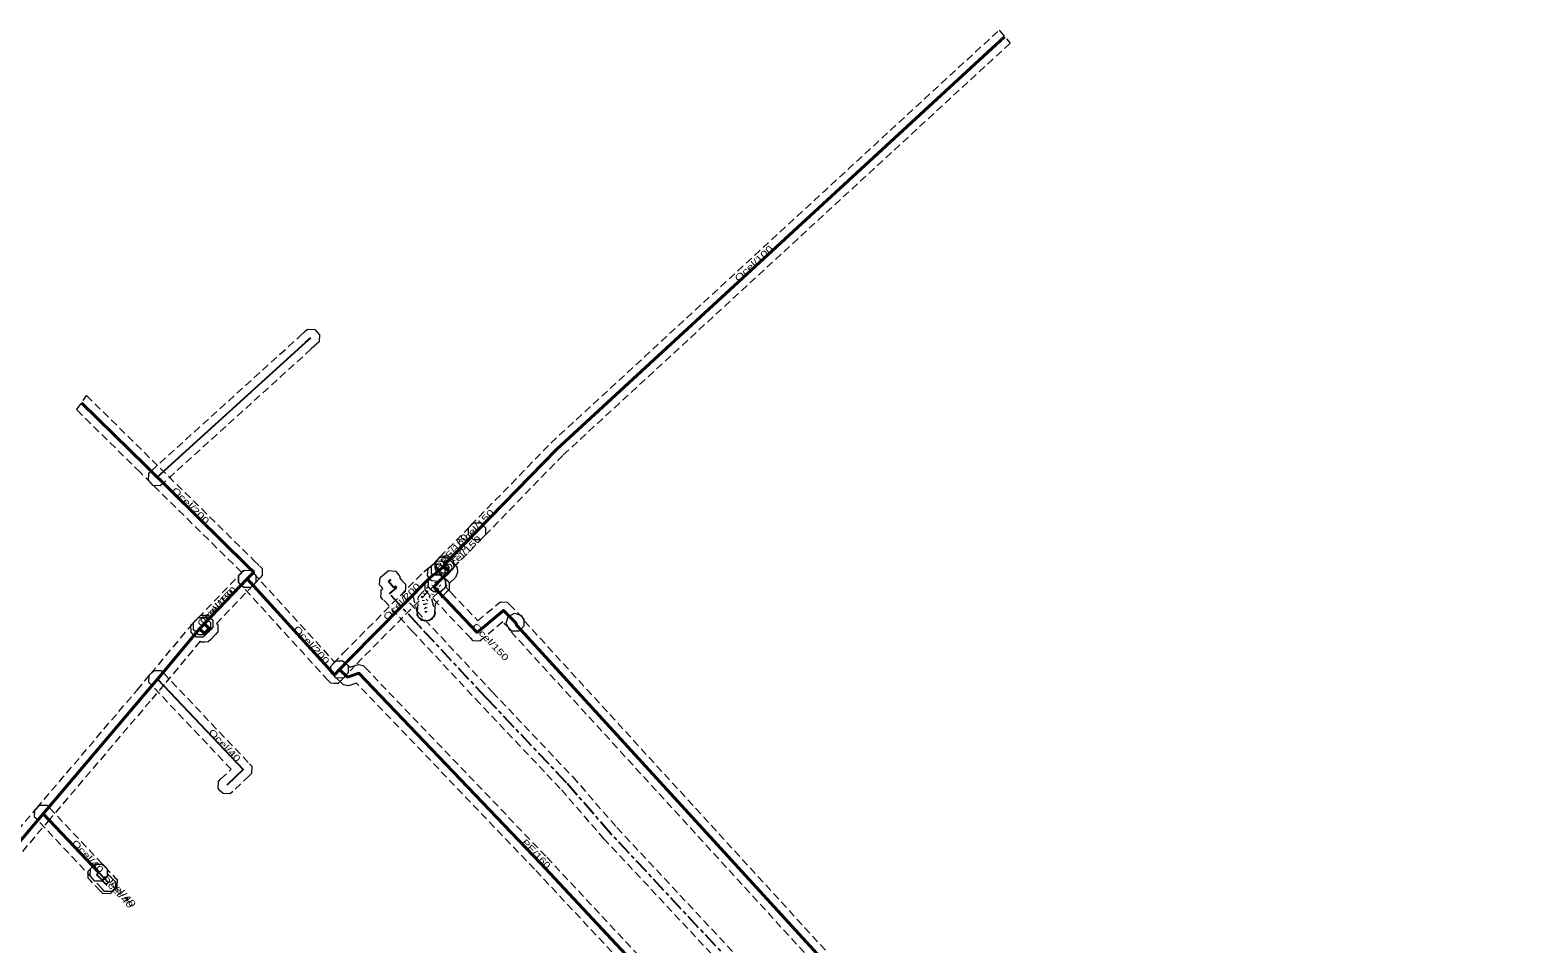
# Model space of a CAD drawing. Extents: x -588392 to -586332, y -1208963 to -1206334.
# Drawn here: x -588303.3 to -588126.9, y -1206440.6 to -1206333.7 of the extents above; entities that cross this region are included whole.
import ezdxf

# ---------------------------------------------------------------- set-up
doc = ezdxf.new("R2010")
doc.units = 0
doc.header["$LTSCALE"] = 0.3
for name, pattern in [('DOTTED', [1.5, 0.3, -1.2]), ('LONG_DASH_SHORT_DASH', [9.9, 6, -1.2, 1.5, -1.2]), ('MEDIUM_DASHED', [4.5, 3, -1.5])]:
    doc.linetypes.add(name, pattern=pattern)
for name, color, linetype, lineweight in [('1', 7, 'MEDIUM_DASHED', 13), ('24', 7, 'Continuous', 25), ('25', 7, 'Continuous', 25), ('51', 7, 'MEDIUM_DASHED', 13), ('55', 7, 'LONG_DASH_SHORT_DASH', 25), ('56', 7, 'DOTTED', 35), ('7', 7, 'MEDIUM_DASHED', 13), ('8', 7, 'MEDIUM_DASHED', 13)]:
    doc.layers.add(name, color=color, linetype=linetype, lineweight=lineweight)
doc.layers.add('30', color=7, linetype='Continuous')

msp = doc.modelspace()

# ---------------------------------------------------------------- linework, layer by layer
at = {"layer": '1'}
for points in [[(-588242.398, -1206381.993), (-588189.949, -1206333.691), (-588188.651, -1206335.214), (-588241.002, -1206383.427), (-588250.323, -1206393.007), (-588250.612, -1206393.304), (-588251.44, -1206393.316), (-588251.737, -1206393.027), (-588252.034, -1206392.738), (-588252.046, -1206391.91), (-588251.757, -1206391.613)], [(-588290.461, -1206385.403), (-588297.883, -1206378.097), (-588296.716, -1206376.439), (-588289.059, -1206383.977), (-588277.168, -1206395.678), (-588276.458, -1206396.378), (-588276.165, -1206396.666), (-588276.154, -1206397.487), (-588276.439, -1206397.783), (-588277.199, -1206398.573), (-588277.486, -1206398.872), (-588278.315, -1206398.888), (-588278.613, -1206398.601), (-588278.912, -1206398.314), (-588278.928, -1206397.485), (-588278.641, -1206397.187), (-588278.566, -1206397.109), (-588278.572, -1206397.102)], [(-588255.814, -1206395.829), (-588255.54, -1206395.518), (-588255.374, -1206395.33), (-588251.757, -1206391.613), (-588251.468, -1206391.316), (-588250.64, -1206391.304), (-588250.343, -1206391.593), (-588250.046, -1206391.882), (-588250.034, -1206392.71), (-588250.323, -1206393.007), (-588253.906, -1206396.69), (-588254.04, -1206396.842), (-588254.314, -1206397.152), (-588255.141, -1206397.204), (-588255.452, -1206396.93), (-588255.762, -1206396.656)], [(-588254.86, -1206397.679), (-588255.183, -1206397.939), (-588255.909, -1206398.524), (-588265.252, -1206407.956), (-588266.385, -1206409.149), (-588266.67, -1206409.449), (-588267.499, -1206409.47), (-588267.799, -1206409.185), (-588268.099, -1206408.9), (-588268.12, -1206408.071), (-588267.835, -1206407.771), (-588266.688, -1206406.564), (-588257.251, -1206397.036), (-588256.437, -1206396.381), (-588256.114, -1206396.121), (-588255.291, -1206396.21), (-588255.031, -1206396.533), (-588254.771, -1206396.856)], [(-588256.764, -1206396.648), (-588256.443, -1206396.386), (-588256.003, -1206396.026), (-588255.682, -1206395.764), (-588254.858, -1206395.846), (-588254.596, -1206396.167), (-588254.334, -1206396.488), (-588254.416, -1206397.312), (-588254.737, -1206397.574), (-588255.177, -1206397.934), (-588255.498, -1206398.196), (-588256.322, -1206398.114), (-588256.584, -1206397.793), (-588256.846, -1206397.472)], [(-588256.358, -1206397.634), (-588256.15, -1206397.431), (-588256.378, -1206397.194), (-588256.362, -1206396.366), (-588256.063, -1206396.079), (-588255.846, -1206395.871), (-588255.687, -1206395.686), (-588255.414, -1206395.37), (-588254.996, -1206395.342), (-588254.579, -1206395.314), (-588254.267, -1206395.592), (-588253.64, -1206396.148), (-588253.488, -1206396.375), (-588253.348, -1206396.585), (-588253.301, -1206397.086), (-588253.398, -1206397.318), (-588253.557, -1206397.694), (-588254.958, -1206399.064), (-588255.01, -1206399.114), (-588255.306, -1206399.404), (-588256.134, -1206399.396), (-588256.424, -1206399.1), (-588256.714, -1206398.804), (-588256.706, -1206397.976), (-588256.41, -1206397.686)], [(-588255.956, -1206395.993), (-588255.683, -1206395.681), (-588255.543, -1206395.521), (-588255.27, -1206395.21), (-588254.443, -1206395.154), (-588254.131, -1206395.427), (-588253.82, -1206395.7), (-588253.764, -1206396.527), (-588254.037, -1206396.839), (-588254.177, -1206396.999), (-588254.45, -1206397.31), (-588255.277, -1206397.366), (-588255.589, -1206397.093), (-588255.9, -1206396.82)], [(-588277.181, -1206397.207), (-588267.694, -1206407.623), (-588267.548, -1206407.47), (-588266.72, -1206407.45), (-588266.42, -1206407.736), (-588266.12, -1206408.022), (-588266.1, -1206408.85), (-588266.386, -1206409.15), (-588266.986, -1206409.78), (-588267.286, -1206410.095), (-588267.721, -1206410.09), (-588268.156, -1206410.085), (-588268.449, -1206409.763), (-588278.659, -1206398.553), (-588278.938, -1206398.247), (-588278.9, -1206397.42), (-588278.593, -1206397.141), (-588278.287, -1206396.862), (-588277.46, -1206396.9)], [(-588254.7, -1206398.79), (-588254.719, -1206398.81), (-588254.154, -1206399.403), (-588254.087, -1206399.473), (-588250.952, -1206402.762), (-588248.591, -1206400.792), (-588248.293, -1206400.544), (-588247.517, -1206400.579), (-588247.243, -1206400.853), (-588245.833, -1206402.263), (-588245.54, -1206402.556), (-588245.54, -1206403.384), (-588245.833, -1206403.677), (-588246.126, -1206403.97), (-588246.954, -1206403.97), (-588247.247, -1206403.677), (-588248.011, -1206402.913), (-588250.389, -1206404.898), (-588250.692, -1206405.151), (-588251.481, -1206405.106), (-588251.754, -1206404.82), (-588255.533, -1206400.855), (-588255.6, -1206400.785), (-588256.465, -1206399.877), (-588256.824, -1206399.5), (-588257.1, -1206399.21), (-588257.1, -1206398.41), (-588256.825, -1206398.121), (-588256.474, -1206397.753), (-588256.434, -1206397.71), (-588256.148, -1206397.41), (-588255.32, -1206397.39), (-588255.02, -1206397.676), (-588254.72, -1206397.962)], [(-588284.503, -1206403.294), (-588284.213, -1206402.999), (-588283.921, -1206402.702), (-588283.631, -1206402.407), (-588282.802, -1206402.4), (-588282.507, -1206402.69), (-588282.212, -1206402.98), (-588282.205, -1206403.809), (-588282.495, -1206404.104), (-588282.787, -1206404.401), (-588283.077, -1206404.696), (-588283.906, -1206404.703), (-588284.201, -1206404.413), (-588284.496, -1206404.123)], [(-588284.212, -1206402.998), (-588283.922, -1206402.702), (-588283.654, -1206402.429), (-588283.364, -1206402.134), (-588282.535, -1206402.126), (-588282.239, -1206402.416), (-588281.944, -1206402.706), (-588281.936, -1206403.535), (-588282.226, -1206403.831), (-588282.494, -1206404.104), (-588282.784, -1206404.399), (-588283.613, -1206404.407), (-588283.909, -1206404.117), (-588284.204, -1206403.827)], [(-588287.979, -1206408.601), (-588287.694, -1206408.902), (-588277.664, -1206419.492), (-588277.379, -1206419.793), (-588277.402, -1206420.621), (-588277.702, -1206420.906), (-588279.622, -1206422.726), (-588279.923, -1206423.011), (-588280.751, -1206422.989), (-588281.036, -1206422.688), (-588281.321, -1206422.387), (-588281.299, -1206421.559), (-588280.998, -1206421.274), (-588279.803, -1206420.142), (-588289.146, -1206410.278), (-588289.431, -1206409.977), (-588289.409, -1206409.149), (-588289.108, -1206408.864), (-588288.807, -1206408.579)], [(-588301.347, -1206424.352), (-588301.063, -1206424.654), (-588294.563, -1206431.544), (-588294.278, -1206431.845), (-588294.302, -1206432.673), (-588294.604, -1206432.957), (-588294.905, -1206433.242), (-588295.733, -1206433.218), (-588296.017, -1206432.916), (-588302.517, -1206426.026), (-588302.802, -1206425.725), (-588302.778, -1206424.897), (-588302.476, -1206424.613), (-588302.175, -1206424.328)], [(-588294.29, -1206431.816), (-588294.29, -1206432.322), (-588293.635, -1206433.011), (-588293.35, -1206433.311), (-588293.371, -1206434.139), (-588293.671, -1206434.425), (-588293.971, -1206434.71), (-588294.799, -1206434.689), (-588295.085, -1206434.389), (-588296.255, -1206433.159), (-588296.535, -1206432.864), (-588296.525, -1206432.051), (-588296.237, -1206431.763), (-588295.997, -1206431.523), (-588295.704, -1206431.23), (-588294.876, -1206431.23), (-588294.583, -1206431.523)], [(-588294.846, -1206431.242), (-588294.562, -1206431.544), (-588293.432, -1206432.744), (-588293.148, -1206433.046), (-588293.172, -1206433.874), (-588293.474, -1206434.158), (-588293.776, -1206434.442), (-588294.604, -1206434.418), (-588294.888, -1206434.116), (-588296.018, -1206432.916), (-588296.302, -1206432.614), (-588296.278, -1206431.786), (-588295.976, -1206431.502), (-588295.674, -1206431.218)]]:
    msp.add_lwpolyline(points, close=True, dxfattribs=at)
for points in [[(-588308.256, -1206431.407), (-588302.552, -1206424.692), (-588290.804, -1206410.875), (-588289.187, -1206408.948), (-588284.267, -1206403.059), (-588283.988, -1206402.725), (-588283.934, -1206402.722), (-588283.663, -1206402.439), (-588278.643, -1206397.189), (-588278.357, -1206396.89), (-588277.528, -1206396.871), (-588277.229, -1206397.157), (-588276.93, -1206397.443), (-588276.911, -1206398.272), (-588277.197, -1206398.571), (-588281.534, -1206403.106), (-588281.372, -1206403.274), (-588281.368, -1206404.077), (-588281.644, -1206404.368), (-588282.194, -1206404.948), (-588282.481, -1206405.251), (-588282.898, -1206405.26), (-588283.315, -1206405.269), (-588283.422, -1206405.166), (-588287.653, -1206410.232), (-588289.276, -1206412.165), (-588301.028, -1206425.988), (-588306.724, -1206432.693)], [(-588105.041, -1206560.272), (-588137.218, -1206521.444), (-588141.774, -1206516.649), (-588169.516, -1206487.445), (-588190.167, -1206465.706), (-588196.423, -1206459.121), (-588203.622, -1206451.542), (-588247.155, -1206403.949), (-588247.425, -1206403.435), (-588247.618, -1206403.068), (-588247.372, -1206402.277), (-588247.005, -1206402.085), (-588246.638, -1206401.892), (-588245.847, -1206402.138), (-588245.655, -1206402.505), (-588245.505, -1206402.791), (-588202.158, -1206450.178), (-588194.973, -1206457.743), (-588188.717, -1206464.328), (-588168.066, -1206486.067), (-588140.324, -1206515.271), (-588135.722, -1206520.116), (-588103.501, -1206558.996)], [(-588226.031, -1206451.373), (-588244.316, -1206431.807), (-588265.143, -1206410.06), (-588265.852, -1206410.298), (-588266.115, -1206410.386), (-588266.656, -1206410.267), (-588266.858, -1206410.076), (-588267.798, -1206409.186), (-588268.099, -1206408.901), (-588268.121, -1206408.073), (-588267.836, -1206407.772), (-588267.551, -1206407.471), (-588266.723, -1206407.449), (-588266.422, -1206407.734), (-588265.919, -1206408.211), (-588265.178, -1206407.962), (-588264.903, -1206407.87), (-588264.339, -1206408.008), (-588264.138, -1206408.218), (-588242.864, -1206430.433), (-588224.569, -1206450.007)]]:
    msp.add_lwpolyline(points, dxfattribs=at)
at = {"layer": '24', "lineweight": 40}
for p, q in [((-588255.81, -1206397.16), (-588255.37, -1206396.8)), ((-588254.93, -1206396.34), (-588254.79, -1206396.18)), ((-588283.5, -1206403.7), (-588283.208, -1206403.403)), ((-588283.208, -1206403.403), (-588282.94, -1206403.13)), ((-588301.79, -1206425.34), (-588295.29, -1206432.23))]:
    msp.add_line(p, q, dxfattribs=at)
at = {"layer": '24'}
msp.add_line((-588295.29, -1206432.23), (-588294.16, -1206433.43), dxfattribs=at)
at = {"layer": '24', "lineweight": 40}
for points in [[(-588189.3, -1206334.453), (-588241.7, -1206382.71), (-588251.04, -1206392.31)], [(-588297.299, -1206377.268), (-588289.76, -1206384.69), (-588277.87, -1206396.39), (-588277.16, -1206397.09), (-588277.92, -1206397.88)], [(-588254.79, -1206396.18), (-588254.64, -1206396.01), (-588251.04, -1206392.31)], [(-588255.37, -1206396.8), (-588255.12, -1206396.56), (-588254.93, -1206396.34), (-588254.4, -1206396.81), (-588254.32, -1206396.93), (-588254.4, -1206397.12), (-588255.658, -1206398.349), (-588255.71, -1206398.4)], [(-588277.92, -1206397.88), (-588282.94, -1206403.13), (-588282.65, -1206403.39), (-588282.37, -1206403.68), (-588282.92, -1206404.26), (-588283.5, -1206403.7), (-588288.42, -1206409.59), (-588290.04, -1206411.52), (-588301.79, -1206425.34), (-588307.49, -1206432.05)], [(-588267.11, -1206408.46), (-588267.71, -1206409.09), (-588277.92, -1206397.88)], [(-588255.81, -1206397.16), (-588256.58, -1206397.78), (-588265.97, -1206407.26), (-588267.11, -1206408.46)], [(-588255.71, -1206398.4), (-588255.75, -1206398.442), (-588256.1, -1206398.81), (-588255.741, -1206399.187), (-588254.877, -1206400.094), (-588254.81, -1206400.164), (-588251.03, -1206404.13), (-588247.95, -1206401.56), (-588246.54, -1206402.97)], [(-588246.54, -1206402.97), (-588246.33, -1206403.37), (-588202.89, -1206450.86), (-588195.698, -1206458.432), (-588189.442, -1206465.017), (-588168.791, -1206486.756), (-588141.049, -1206515.96), (-588136.47, -1206520.78), (-588104.271, -1206559.634), (-588072.7, -1206597.73), (-588057.802, -1206615.664), (-588044.559, -1206631.23)], [(-588267.11, -1206408.46), (-588266.17, -1206409.35), (-588264.86, -1206408.91), (-588243.59, -1206431.12), (-588225.3, -1206450.69)]]:
    msp.add_lwpolyline(points, dxfattribs=at)
at = {"layer": '24'}
for points in [[(-588288.42, -1206409.59), (-588278.39, -1206420.18), (-588280.31, -1206422)], [(-588295.29, -1206432.23), (-588295.53, -1206432.47), (-588294.36, -1206433.7)]]:
    msp.add_lwpolyline(points, dxfattribs=at)
at = {"layer": '25'}
msp.add_lwpolyline([(-588288.463, -1206385.967), (-588271.1, -1206370.237), (-588270.49, -1206369.684)], dxfattribs=at)
at = {"layer": '51'}
msp.add_lwpolyline([(-588289.441, -1206385.504), (-588289.134, -1206385.226), (-588271.772, -1206369.496), (-588271.162, -1206368.943), (-588270.855, -1206368.665), (-588270.027, -1206368.705), (-588269.749, -1206369.012), (-588269.471, -1206369.319), (-588269.511, -1206370.147), (-588269.818, -1206370.425), (-588270.428, -1206370.978), (-588287.792, -1206386.708), (-588288.099, -1206386.986), (-588288.926, -1206386.945), (-588289.204, -1206386.638), (-588289.482, -1206386.331)], close=True, dxfattribs=at)
at = {"layer": '55'}
msp.add_lwpolyline([(-588123.14, -1206547.36), (-588143.33, -1206524.83), (-588155.31, -1206511.27), (-588162.09, -1206504), (-588171.42, -1206494.14), (-588172.31, -1206493.7), (-588177.41, -1206487.9), (-588178.08, -1206487.18), (-588188.87, -1206475.5), (-588201.54, -1206462.7), (-588206.44, -1206458.14), (-588221.05, -1206443.01), (-588235.4, -1206427.64), (-588240.56, -1206421.71), (-588249.95, -1206411.8), (-588257.85, -1206403.33), (-588261.263, -1206399.627), (-588260.42, -1206398.88), (-588260.56, -1206398.73), (-588260.763, -1206398.901), (-588261.398, -1206398.196), (-588261.08, -1206397.93)], dxfattribs=at)
at = {"layer": '56'}
for points in [[(-588255.75, -1206398.442), (-588255.858, -1206398.343), (-588257.457, -1206399.91), (-588256.998, -1206401.752)], [(-588256.998, -1206401.752), (-588256.907, -1206400.352), (-588255.297, -1206398.734), (-588255.659, -1206398.357), (-588255.71, -1206398.4)]]:
    msp.add_lwpolyline(points, dxfattribs=at)
at = {"layer": '7'}
for points in [[(-588123.889, -1206548.022), (-588144.077, -1206525.495), (-588156.051, -1206511.942), (-588162.819, -1206504.685), (-588172.023, -1206494.957), (-588172.93, -1206494.509), (-588178.152, -1206488.571), (-588178.813, -1206487.86), (-588189.593, -1206476.191), (-588202.236, -1206463.418), (-588207.141, -1206458.854), (-588221.775, -1206443.699), (-588236.143, -1206428.31), (-588241.3, -1206422.382), (-588250.679, -1206412.485), (-588258.583, -1206404.01), (-588261.998, -1206400.305), (-588262.283, -1206399.996), (-588262.262, -1206399.577), (-588262.241, -1206399.157), (-588262.039, -1206398.979), (-588262.141, -1206398.865), (-588262.425, -1206398.549), (-588262.396, -1206398.126)], [(-588262.396, -1206398.126), (-588262.366, -1206397.702), (-588262.04, -1206397.429), (-588261.722, -1206397.163), (-588261.404, -1206396.897), (-588260.579, -1206396.97), (-588260.313, -1206397.288), (-588260.047, -1206397.606)], [(-588260.047, -1206397.606), (-588260.064, -1206397.796), (-588259.829, -1206398.048), (-588259.689, -1206398.198), (-588259.401, -1206398.506), (-588259.421, -1206398.927), (-588259.441, -1206399.349), (-588259.757, -1206399.628), (-588259.837, -1206399.699), (-588257.117, -1206402.65), (-588249.221, -1206411.115), (-588239.82, -1206421.038), (-588234.657, -1206426.97), (-588220.325, -1206442.321)]]:
    msp.add_lwpolyline(points, dxfattribs=at)
at = {"layer": '8'}
for points in [[(-588255.293, -1206399.423), (-588255.542, -1206399.434), (-588256.348, -1206400.224), (-588256.028, -1206401.51), (-588255.928, -1206401.912), (-588256.354, -1206402.622), (-588256.756, -1206402.722), (-588257.158, -1206402.822), (-588257.868, -1206402.396), (-588257.968, -1206401.994), (-588258.427, -1206400.152), (-588258.492, -1206399.894), (-588258.347, -1206399.382), (-588258.157, -1206399.196), (-588256.558, -1206397.629), (-588256.273, -1206397.35), (-588255.476, -1206397.336), (-588255.182, -1206397.606), (-588255.074, -1206397.705), (-588254.769, -1206397.985), (-588254.733, -1206398.813), (-588255.013, -1206399.118)], [(-588257.881, -1206399.913), (-588256.724, -1206398.75), (-588256.742, -1206398.728), (-588256.671, -1206397.902), (-588256.355, -1206397.635), (-588256.304, -1206397.592), (-588256.002, -1206397.337), (-588255.212, -1206397.379), (-588254.938, -1206397.664), (-588254.576, -1206398.041), (-588254.294, -1206398.335), (-588254.301, -1206399.15), (-588254.588, -1206399.439), (-588255.933, -1206400.791), (-588256, -1206401.817), (-588256.027, -1206402.23), (-588256.65, -1206402.777), (-588257.063, -1206402.75), (-588257.476, -1206402.723), (-588258.023, -1206402.1), (-588257.996, -1206401.687)]]:
    msp.add_lwpolyline(points, close=True, dxfattribs=at)

# ---------------------------------------------------------------- texts
at = {"layer": '30'}
for s, rotation, width, p in [('Ocel/100', 42.643, 1.4, (-588220.463, -1206363.152)), ('Ocel/200', 315.461, 1.4, (-588286.804, -1206387.599)), ('Ocel/150', 45.785, 1.4, (-588252.884, -1206394.205)), ('PE/160', 48.814, 1.3, (-588254.827, -1206396.222)), ('Ocel/150', 44.332, 1.4, (-588254.484, -1206397.202)), ('PE/160', 39.289, 1.3, (-588255.552, -1206396.948)), ('Ocel/200', 45.273, 1.4, (-588261.545, -1206402.792)), ('Ocel/150', 45.486, 1.4, (-588283.319, -1206403.516)), ('Ocel/150', 45.53, 1.4, (-588283.039, -1206403.231)), ('Ocel/200', 312.327, 1.4, (-588272.556, -1206403.769)), ('Ocel/150', 313.624, 1.4, (-588251.654, -1206403.475)), ('Ocel/40', 313.444, 1.4, (-588282.495, -1206415.845)), ('Ocel/40', 313.332, 1.4, (-588298.505, -1206428.821)), ('PE/160', 313.762, 1.3, (-588245.852, -1206428.757)), ('Ocel/40', 313.568, 1.4, (-588295.062, -1206432.962)), ('Ocel/40', 313.279, 1.4, (-588294.725, -1206432.83))]:
    msp.add_text(s, height=0.75, rotation=rotation, dxfattribs=dict(at, width=width)).set_placement(p)

doc.saveas('drawing.dxf')
